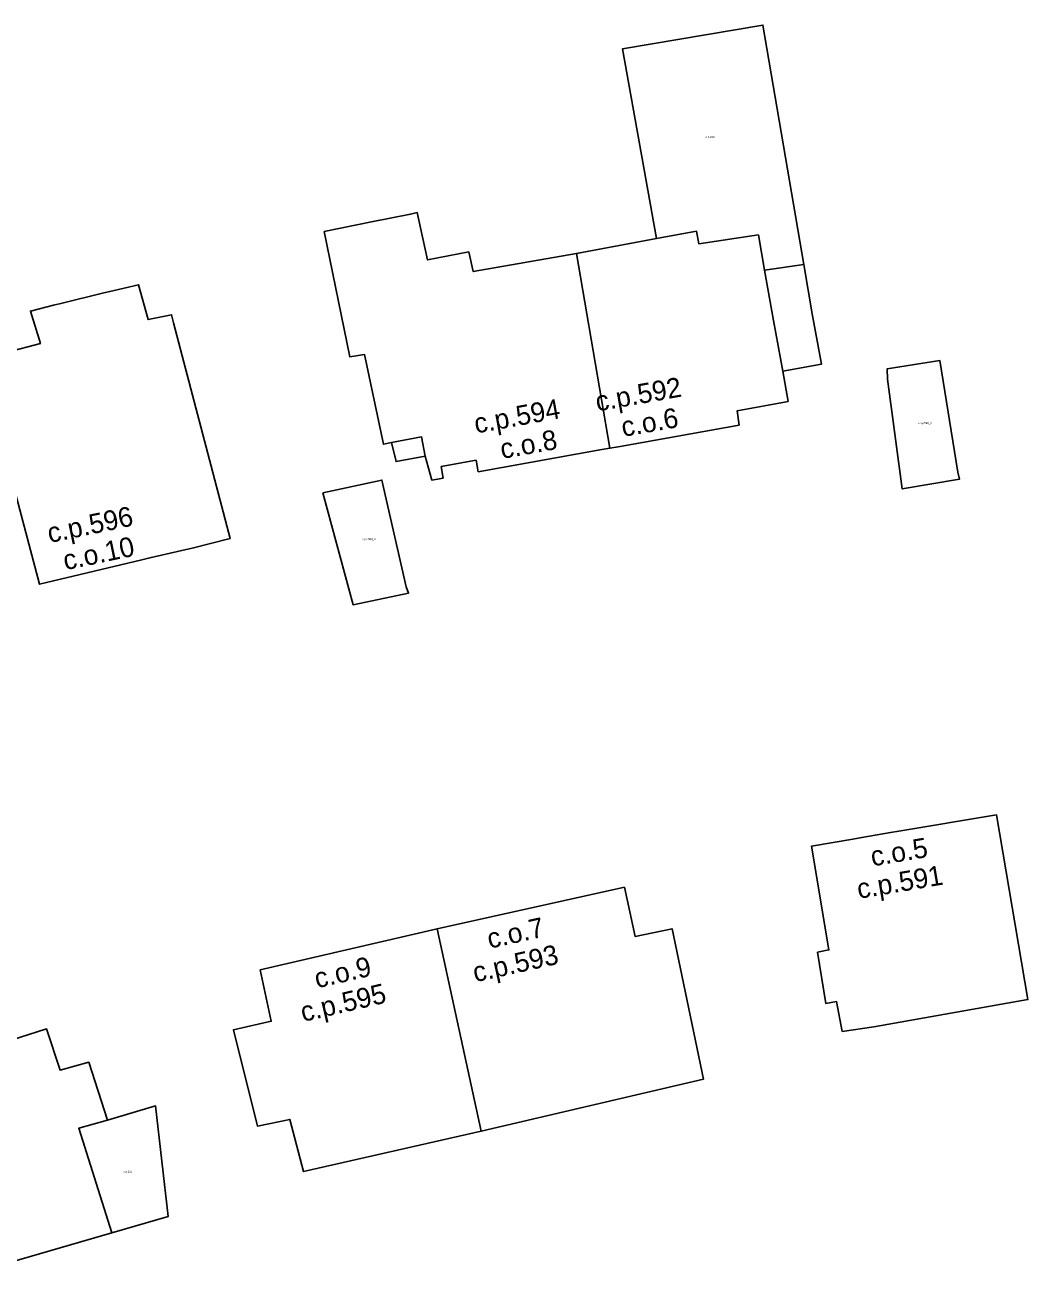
# Model space of a CAD drawing. Extents: x -600391 to -599491, y -1160176 to -1159402.
# Drawn here: x -600144.5 to -600093.7, y -1159661.4 to -1159598 of the extents above; entities that cross this region are included whole.
import ezdxf

# ---------------------------------------------------------------- set-up
doc = ezdxf.new("R2010")
doc.units = 0
for name, color, linetype in [('Level 10', 7, 'Continuous'), ('Level 12', 7, 'Continuous'), ('Level 24', 7, 'Continuous'), ('Level 25', 7, 'Continuous'), ('Level 61', 7, 'Continuous'), ('Level 62', 7, 'Continuous')]:
    doc.layers.add(name, color=color, linetype=linetype)

msp = doc.modelspace()

# ---------------------------------------------------------------- linework, layer by layer
at = {"layer": 'Level 61'}
for points in [[(-600114.24, -1159599.17), (-600107.13, -1159597.96)], [(-600107.13, -1159597.96), (-600105.06, -1159610.07)], [(-600112.51, -1159608.76), (-600114.24, -1159599.17)], [(-600126.94, -1159607.92), (-600124.97, -1159607.52)], [(-600124.97, -1159607.52), (-600124.62, -1159607.45)], [(-600124.62, -1159607.45), (-600124.45, -1159608.22)], [(-600129.33, -1159608.41), (-600127.68, -1159608.07)], [(-600128.04, -1159614.74), (-600129.33, -1159608.41)], [(-600127.68, -1159608.07), (-600126.94, -1159607.92)], [(-600124.45, -1159608.22), (-600124.1, -1159609.84)], [(-600112.51, -1159608.76), (-600110.49, -1159608.39)], [(-600110.49, -1159608.39), (-600112.51, -1159608.76)], [(-600110.49, -1159608.39), (-600110.37, -1159609.03)], [(-600110.37, -1159609.03), (-600110.49, -1159608.39)], [(-600116.57, -1159609.52), (-600112.51, -1159608.76)], [(-600110.37, -1159609.03), (-600107.36, -1159608.58)], [(-600107.36, -1159608.58), (-600110.37, -1159609.03)], [(-600107.36, -1159608.58), (-600107.05, -1159610.36)], [(-600107.05, -1159610.36), (-600107.36, -1159608.58)], [(-600124.1, -1159609.84), (-600122.01, -1159609.44)], [(-600122.01, -1159609.44), (-600121.79, -1159610.43)], [(-600121.79, -1159610.43), (-600116.57, -1159609.52)], [(-600114.87, -1159619.37), (-600116.57, -1159609.52)], [(-600116.57, -1159609.52), (-600114.87, -1159619.37)], [(-600107.05, -1159610.36), (-600105.06, -1159610.07)], [(-600105.06, -1159610.07), (-600107.05, -1159610.36)], [(-600107.05, -1159610.36), (-600106.59, -1159612.91)], [(-600106.59, -1159612.91), (-600107.05, -1159610.36)], [(-600105.06, -1159610.07), (-600104.63, -1159612.57)], [(-600142.66, -1159612.05), (-600140.55, -1159611.53)], [(-600140.55, -1159611.53), (-600140.18, -1159611.44)], [(-600140.18, -1159611.44), (-600138.73, -1159611.1)], [(-600138.73, -1159611.1), (-600138.23, -1159612.86)], [(-600144.19, -1159612.43), (-600143.03, -1159612.14)], [(-600143.03, -1159612.14), (-600142.66, -1159612.05)], [(-600143.69, -1159614.07), (-600144.19, -1159612.43)], [(-600138.23, -1159612.86), (-600137.05, -1159612.62)], [(-600137.05, -1159612.62), (-600136.95, -1159613.02)], [(-600106.59, -1159612.91), (-600106.13, -1159615.47)], [(-600106.13, -1159615.47), (-600106.59, -1159612.91)], [(-600104.63, -1159612.57), (-600104.17, -1159615.12)], [(-600136.95, -1159613.02), (-600134.08, -1159623.94)], [(-600145.35, -1159614.51), (-600143.69, -1159614.07)], [(-600127.29, -1159614.62), (-600128.04, -1159614.74)], [(-600126.33, -1159619.17), (-600127.29, -1159614.62)], [(-600104.17, -1159615.12), (-600106.13, -1159615.47)], [(-600100.84, -1159615.35), (-600098.18, -1159614.93)], [(-600100.82, -1159615.87), (-600100.84, -1159615.35)], [(-600098.18, -1159614.93), (-600097.26, -1159620.59)], [(-600106.13, -1159615.47), (-600105.86, -1159617)], [(-600100.08, -1159621.43), (-600100.82, -1159615.87)], [(-600105.86, -1159617), (-600108.44, -1159617.48)], [(-600143.73, -1159626.25), (-600146.06, -1159617.52)], [(-600108.44, -1159617.48), (-600108.34, -1159618.2)], [(-600108.34, -1159618.2), (-600114.35, -1159619.28)], [(-600125.92, -1159619.08), (-600126.33, -1159619.17)], [(-600124.4, -1159618.8), (-600125.92, -1159619.08)], [(-600125.92, -1159619.08), (-600124.4, -1159618.8)], [(-600125.69, -1159620.05), (-600125.92, -1159619.08)], [(-600124.22, -1159619.78), (-600124.4, -1159618.8)], [(-600124.4, -1159618.8), (-600124.22, -1159619.78)], [(-600124.22, -1159619.78), (-600125.69, -1159620.05)], [(-600123.88, -1159620.98), (-600124.22, -1159619.78)], [(-600115.28, -1159619.44), (-600121.53, -1159620.56)], [(-600114.87, -1159619.37), (-600115.28, -1159619.44)], [(-600114.35, -1159619.28), (-600114.87, -1159619.37)], [(-600121.64, -1159619.98), (-600123.41, -1159620.3)], [(-600123.41, -1159620.3), (-600123.31, -1159620.88)], [(-600121.53, -1159620.56), (-600121.64, -1159619.98)], [(-600129.39, -1159621.63), (-600126.41, -1159620.98)], [(-600126.41, -1159620.98), (-600125.18, -1159626.39)], [(-600123.31, -1159620.88), (-600123.88, -1159620.98)], [(-600097.19, -1159620.94), (-600100.08, -1159621.43)], [(-600097.26, -1159620.59), (-600097.19, -1159620.94)], [(-600127.86, -1159627.29), (-600129.39, -1159621.63)], [(-600134.08, -1159623.94), (-600136.01, -1159624.42)], [(-600138.15, -1159624.92), (-600138.55, -1159625.01)], [(-600136.54, -1159624.54), (-600138.15, -1159624.92)], [(-600136.01, -1159624.42), (-600136.54, -1159624.54)], [(-600138.55, -1159625.01), (-600143.73, -1159626.25)], [(-600125.06, -1159626.7), (-600127.86, -1159627.29)], [(-600125.18, -1159626.39), (-600125.06, -1159626.7)], [(-600100.26, -1159638.75), (-600095.31, -1159637.92)], [(-600095.31, -1159637.92), (-600093.72, -1159647.27)], [(-600102.13, -1159639.07), (-600100.68, -1159638.82)], [(-600100.68, -1159638.82), (-600100.26, -1159638.75)], [(-600104.67, -1159639.5), (-600102.58, -1159639.15)], [(-600103.79, -1159644.75), (-600104.67, -1159639.5)], [(-600102.58, -1159639.15), (-600102.13, -1159639.07)], [(-600123.62, -1159643.68), (-600114.14, -1159641.58)], [(-600114.14, -1159641.58), (-600113.6, -1159644.07)], [(-600132.57, -1159645.76), (-600123.62, -1159643.68)], [(-600123.62, -1159643.68), (-600121.38, -1159653.93)], [(-600121.38, -1159653.93), (-600123.62, -1159643.68)], [(-600113.6, -1159644.07), (-600111.73, -1159643.68)], [(-600111.73, -1159643.68), (-600110.14, -1159651.3)], [(-600104.36, -1159644.87), (-600103.79, -1159644.75)], [(-600103.95, -1159647.46), (-600104.36, -1159644.87)], [(-600132.01, -1159648.36), (-600132.57, -1159645.76)], [(-600103.4, -1159647.37), (-600103.95, -1159647.46)], [(-600103.12, -1159648.88), (-600103.4, -1159647.37)], [(-600093.72, -1159647.27), (-600101.52, -1159648.64)], [(-600133.92, -1159648.79), (-600132.01, -1159648.36)], [(-600144.74, -1159649.19), (-600143.38, -1159648.75)], [(-600143.38, -1159648.75), (-600142.69, -1159650.83)], [(-600132.71, -1159653.67), (-600133.92, -1159648.79)], [(-600101.52, -1159648.64), (-600103.12, -1159648.88)], [(-600142.69, -1159650.83), (-600141.24, -1159650.44)], [(-600141.24, -1159650.44), (-600140.3, -1159653.36)], [(-600110.14, -1159651.3), (-600121.38, -1159653.93)], [(-600140.3, -1159653.36), (-600137.86, -1159652.65)], [(-600137.86, -1159652.65), (-600137.22, -1159658.24)], [(-600140.3, -1159653.36), (-600141.75, -1159653.78)], [(-600141.75, -1159653.78), (-600140.3, -1159653.36)], [(-600131.07, -1159653.33), (-600132.71, -1159653.67)], [(-600130.38, -1159655.97), (-600131.07, -1159653.33)], [(-600141.75, -1159653.78), (-600140.07, -1159659.07)], [(-600140.07, -1159659.07), (-600141.75, -1159653.78)], [(-600121.38, -1159653.93), (-600130.38, -1159655.97)], [(-600137.22, -1159658.24), (-600140.07, -1159659.07)], [(-600140.07, -1159659.07), (-600147.93, -1159661.35)]]:
    msp.add_lwpolyline(points, dxfattribs=at)
at = {"layer": 'Level 62'}
for points in [[(-600112.51, -1159608.76), (-600114.24, -1159599.17), (-600107.13, -1159597.96), (-600105.06, -1159610.07), (-600107.05, -1159610.36), (-600107.36, -1159608.58), (-600110.37, -1159609.03), (-600110.49, -1159608.39), (-600112.51, -1159608.76)], [(-600122.01, -1159609.44), (-600121.79, -1159610.43), (-600116.57, -1159609.52), (-600114.87, -1159619.37), (-600115.28, -1159619.44), (-600121.53, -1159620.56), (-600121.64, -1159619.98), (-600123.41, -1159620.3), (-600123.31, -1159620.88), (-600123.88, -1159620.98), (-600124.22, -1159619.78), (-600124.4, -1159618.8), (-600125.92, -1159619.08), (-600126.33, -1159619.17), (-600127.29, -1159614.62), (-600128.04, -1159614.74), (-600129.33, -1159608.41), (-600127.68, -1159608.07), (-600126.94, -1159607.92), (-600124.97, -1159607.52), (-600124.62, -1159607.45), (-600124.45, -1159608.22), (-600124.1, -1159609.84), (-600122.01, -1159609.44)], [(-600114.35, -1159619.28), (-600114.87, -1159619.37), (-600116.57, -1159609.52), (-600112.51, -1159608.76), (-600110.49, -1159608.39), (-600110.37, -1159609.03), (-600107.36, -1159608.58), (-600107.05, -1159610.36), (-600106.59, -1159612.91), (-600106.13, -1159615.47), (-600105.86, -1159617), (-600108.44, -1159617.48), (-600108.34, -1159618.2), (-600114.35, -1159619.28)], [(-600106.13, -1159615.47), (-600106.59, -1159612.91), (-600107.05, -1159610.36), (-600105.06, -1159610.07), (-600104.63, -1159612.57), (-600104.17, -1159615.12), (-600106.13, -1159615.47)], [(-600142.66, -1159612.05), (-600140.55, -1159611.53), (-600140.18, -1159611.44), (-600138.73, -1159611.1), (-600138.23, -1159612.86), (-600137.05, -1159612.62), (-600136.95, -1159613.02), (-600134.08, -1159623.94), (-600136.01, -1159624.42), (-600136.54, -1159624.54), (-600138.15, -1159624.92), (-600138.55, -1159625.01), (-600143.73, -1159626.25), (-600146.06, -1159617.52), (-600146.57, -1159617.59), (-600146.86, -1159616.43), (-600145.35, -1159614.51), (-600143.69, -1159614.07), (-600144.19, -1159612.43), (-600143.03, -1159612.14), (-600142.66, -1159612.05)], [(-600097.26, -1159620.59), (-600097.19, -1159620.94), (-600100.08, -1159621.43), (-600100.82, -1159615.87), (-600100.84, -1159615.35), (-600098.18, -1159614.93), (-600097.26, -1159620.59)], [(-600124.22, -1159619.78), (-600125.69, -1159620.05), (-600125.92, -1159619.08), (-600124.4, -1159618.8), (-600124.22, -1159619.78)], [(-600129.39, -1159621.63), (-600126.41, -1159620.98), (-600125.18, -1159626.39), (-600125.06, -1159626.7), (-600127.86, -1159627.29), (-600129.39, -1159621.63)], [(-600102.58, -1159639.15), (-600102.13, -1159639.07), (-600100.68, -1159638.82), (-600100.26, -1159638.75), (-600095.31, -1159637.92), (-600093.72, -1159647.27), (-600101.52, -1159648.64), (-600103.12, -1159648.88), (-600103.4, -1159647.37), (-600103.95, -1159647.46), (-600104.36, -1159644.87), (-600103.79, -1159644.75), (-600104.67, -1159639.5), (-600102.58, -1159639.15)], [(-600114.14, -1159641.58), (-600113.6, -1159644.07), (-600111.73, -1159643.68), (-600110.14, -1159651.3), (-600121.38, -1159653.93), (-600123.62, -1159643.68), (-600114.14, -1159641.58)], [(-600132.57, -1159645.76), (-600123.62, -1159643.68), (-600121.38, -1159653.93), (-600130.38, -1159655.97), (-600131.07, -1159653.33), (-600132.71, -1159653.67), (-600133.92, -1159648.79), (-600132.01, -1159648.36), (-600132.57, -1159645.76)], [(-600146.13, -1159649.64), (-600144.74, -1159649.19), (-600143.38, -1159648.75), (-600142.69, -1159650.83), (-600141.24, -1159650.44), (-600140.3, -1159653.36), (-600141.75, -1159653.78), (-600140.07, -1159659.07), (-600147.93, -1159661.35), (-600148.97, -1159658.44), (-600149.59, -1159656.7), (-600151.51, -1159651.33), (-600146.13, -1159649.64)], [(-600140.07, -1159659.07), (-600141.75, -1159653.78), (-600140.3, -1159653.36), (-600137.86, -1159652.65), (-600137.22, -1159658.24), (-600140.07, -1159659.07)]]:
    msp.add_lwpolyline(points, dxfattribs=at)

# ---------------------------------------------------------------- texts
at = {"layer": 'Level 10'}
for s, rotation, p in [('c.o.6', 10.04913, (-600114.202, -1159618.799)), ('c.o.8', 10.29408, (-600120.327, -1159619.915)), ('c.o.10', 11.81784, (-600142.427, -1159625.546)), ('c.o.5', 9.61303, (-600101.589, -1159640.529)), ('c.o.7', 12.47971, (-600120.961, -1159644.693)), ('c.o.9', 13.09682, (-600129.695, -1159646.701))]:
    msp.add_text(s, height=1, rotation=rotation, dxfattribs=at).set_placement(p)
at = {"layer": 'Level 12'}
for s, rotation, p in [('c.p.592', 10.04913, (-600115.507, -1159617.511)), ('c.p.594', 10.29408, (-600121.647, -1159618.626)), ('c.p.596', 11.81784, (-600143.223, -1159624.169)), ('c.p.591', 9.61303, (-600102.281, -1159642.171)), ('c.p.593', 12.47971, (-600121.688, -1159646.392)), ('c.p.595', 13.09682, (-600130.395, -1159648.4))]:
    msp.add_text(s, height=1, rotation=rotation, dxfattribs=at).set_placement(p)
at = {"layer": 'Level 24'}
for s, p in [('c.z.213', (-600110.029, -1159603.667)), ('c.z.133', (-600139.489, -1159656.017))]:
    msp.add_text(s, height=0.1, dxfattribs=at).set_placement(p)
at = {"layer": 'Level 25'}
for s, p in [('c.pp.590_A', (-600099.273, -1159618.147)), ('c.pp.594_A', (-600127.413, -1159624.017))]:
    msp.add_text(s, height=0.1, dxfattribs=at).set_placement(p)

doc.saveas('drawing.dxf')
